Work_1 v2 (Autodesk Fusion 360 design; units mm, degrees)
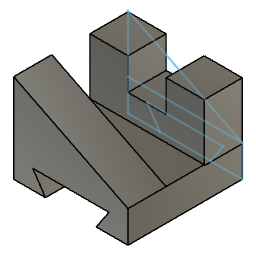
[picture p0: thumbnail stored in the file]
sketch "Sketch1" plane through (0, 0, 0) normal (0, 1, 0) x axis (1, 0, 0)
  line L1 (-40, -70) -> (-100, -70)
  line L2 (-50.0002, -55) -> (-90.0002, -55)
  line L3 (-50.0002, -55) -> (-40, -70)
  line L4 (-90.0002, -55) -> (-100, -70)
  line L5 (-25.0002, -55) -> (-50.0002, -55)
  line L6 (-115.0002, -55) -> (-90.0002, -55)
  line L7 (-115.0002, -55) -> (-115.0002, -80)
  line L8 (-25.0002, -55) -> (-25.0002, -80)
  line L9 (-25.0002, -80) -> (-115.0002, -80)
  line L10 (-115.0002, -125) -> (-115.0002, -80)
  line L11 (-25.0002, -80) -> (-115.0002, -125)
  point P4 (-90.0002, -55)
  point P5 (-50.0002, -55)
  point P6 (-25.0002, -55)
  point P7 (-115.0002, -55)
  point P1 (0, 0)
  point P8 (-115.0002, -80)
  point P10 (-115.0002, -125)
  horizontal L1
  perpendicular L6 L7
  perpendicular L5 L8
  perpendicular L8 L9
  dimension "d3" distance P4 P5 = 40
  dimension "d4" distance P5 P6 = 25
  dimension "d5" distance P4 P7 = 25
  dimension "d6" distance P1 L2 = 55
  dimension "d7" distance P1 L9 = 80
  dimension "d8" distance P1 L8 = 25.0002
  dimension "d9" distance P1 L7 = 115.0002
  dimension "d12" distance P8 P10 = 45
extrude "Extrude1" new body sketch "Sketch1" profile of L1 L3 L4 L5 L6 L7 L8 L9 along normal blind 90
extrude "Extrude2" add sketch "Sketch1" profile of L9 L10 L11 along normal blind 30
sketch "Sketch2" plane through (0, 0, 0) normal (0, 1, 0) x axis (1, 0, 0)
  line L1 (-114.9814, -124.2605) -> (-114.9814, -79.2605)
  line L2 (-24.9814, -79.2605) -> (-114.9814, -79.2605)
  line L3 (-54.9814, -124.2605) -> (-24.9814, -124.2605)
  line L4 (-54.9814, -99.2605) -> (-54.9814, -124.2605)
  line L5 (-84.9814, -99.2605) -> (-54.9814, -99.2605)
  line L6 (-84.9814, -124.2605) -> (-84.9814, -99.2605)
  line L7 (-114.9814, -124.2605) -> (-84.9814, -124.2605)
  line L8 (-24.9814, -79.2605) -> (-24.9814, -101.7605)
  line L9 (-24.9814, -124.2605) -> (-24.9814, -101.7605)
  point P2 (-114.9814, -79.2605)
  point P3 (-114.9814, -124.2605)
  point P4 (-24.9814, -79.2605)
  point P5 (-24.9814, -124.2605)
  point P6 (-54.9814, -124.2605)
  point P7 (-54.9814, -99.2605)
  point P8 (-84.9814, -99.2605)
  point P9 (-84.9814, -124.2605)
  point P11 (-24.9814, -101.7605)
  point P10 (-24.9814, -101.7605)
  vertical L1
  perpendicular L1 L2
  perpendicular L3 L4
  perpendicular L4 L5
  perpendicular L5 L6
  perpendicular L1 L7
  perpendicular L3 L9
  dimension "d15" distance P2 P3 = 45
  dimension "d16" distance P2 P4 = 90
  dimension "d18" distance P5 P6 = 30
  dimension "d19" distance P6 P7 = 25
  dimension "d20" distance P7 P8 = 30
  dimension "d21" distance P8 P9 = 25
  dimension "d22" distance P5 P11 = 22.5
  dimension "d23" distance P4 P10 = 22.5
move "Move1"
extrude "Extrude3" add sketch "Sketch2" against normal blind 30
